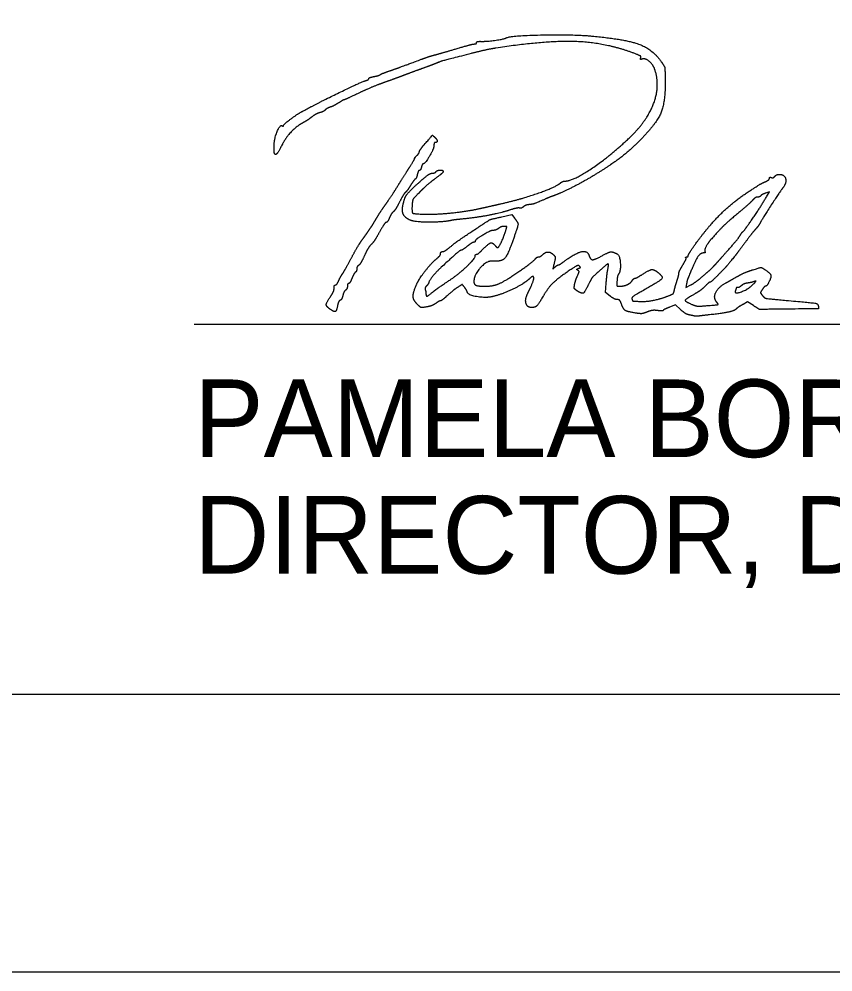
# Model space of a CAD drawing. Extents: x -21.1 to 50.3, y -4.9 to 22.1.
# Drawn here: x 24.436 to 25.904, y 0 to 1.718 of the extents above; entities that cross this region are included whole.
import ezdxf

# ---------------------------------------------------------------- set-up
doc = ezdxf.new("R2010")
doc.units = 0
for name, color, linetype in [('Default', 7, 'Continuous'), ('SH_Border', 7, 'Continuous'), ('SH_Cut_Line', 7, 'Continuous'), ('SH_Data', 7, 'Continuous'), ('SH_Text', 7, 'Continuous')]:
    doc.layers.add(name, color=color, linetype=linetype)

msp = doc.modelspace()

# ---------------------------------------------------------------- linework, layer by layer
at = {"layer": 'Default'}
for points in [[(25.7841, 1.3975), (25.7895, 1.4065), (25.7822, 1.4039)], [(25.3068, 1.3614), (25.3248, 1.3654), (25.3295, 1.3592)], [(25.5018, 1.2186), (25.4934, 1.2249), (25.4949, 1.242)], [(25.6398, 1.2406), (25.6387, 1.2341), (25.6474, 1.2385)], [(25.7606, 1.2012), (25.7499, 1.208), (25.7416, 1.2035)], [(25.6287, 1.1942), (25.6196, 1.2025), (25.609, 1.1984)]]:
    msp.add_lwpolyline(points, dxfattribs=at)
for points in [[(25.2702, 1.6777), (25.2798, 1.6775), (25.3108, 1.6818), (25.3142, 1.6839)], [(25.3142, 1.6839), (25.321, 1.6881), (25.438, 1.6904), (25.4724, 1.687)], [(25.4724, 1.687), (25.5317, 1.6812), (25.5792, 1.6629), (25.595, 1.6399)], [(25.2245, 1.6644), (25.2406, 1.6691), (25.2554, 1.673), (25.2575, 1.673)], [(25.2575, 1.673), (25.2595, 1.673), (25.2612, 1.6741), (25.2612, 1.6755)], [(25.2612, 1.6755), (25.2612, 1.6769), (25.2653, 1.6779), (25.2702, 1.6777)], [(25.5449, 1.6563), (25.4944, 1.6753), (25.3864, 1.6793), (25.296, 1.6655)], [(25.1616, 1.6454), (25.1696, 1.6483), (25.1804, 1.6519), (25.1856, 1.6532)], [(25.1856, 1.6532), (25.1909, 1.6546), (25.2084, 1.6596), (25.2245, 1.6644)], [(25.2516, 1.6558), (25.2006, 1.6426), (25.1963, 1.6414), (25.1856, 1.637)], [(25.296, 1.6655), (25.2868, 1.6641), (25.2668, 1.6597), (25.2516, 1.6558)], [(25.5572, 1.6477), (25.5582, 1.6502), (25.5548, 1.6526), (25.5449, 1.6563)], [(25.1052, 1.6248), (25.1199, 1.6299), (25.1264, 1.6322), (25.1616, 1.6454)], [(25.1856, 1.637), (25.183, 1.636), (25.1727, 1.6321), (25.1628, 1.6285)], [(25.5596, 1.6456), (25.557, 1.6446), (25.5563, 1.6452), (25.5572, 1.6477)], [(25.583, 1.6257), (25.5798, 1.6355), (25.5653, 1.6478), (25.5596, 1.6456)], [(25.595, 1.6399), (25.6, 1.6326), (25.6009, 1.6283), (25.6012, 1.6104)], [(25.0758, 1.6142), (25.0808, 1.6151), (25.0859, 1.6166), (25.0872, 1.6176)], [(25.0872, 1.6176), (25.0886, 1.6186), (25.0967, 1.6218), (25.1052, 1.6248)], [(25.1292, 1.6161), (25.1207, 1.6129), (25.1045, 1.607), (25.0932, 1.603)], [(25.1628, 1.6285), (25.1529, 1.625), (25.1378, 1.6194), (25.1292, 1.6161)], [(25.5375, 1.5045), (25.5685, 1.5339), (25.5923, 1.5974), (25.583, 1.6257)], [(24.9492, 1.5526), (24.9795, 1.5689), (25.0531, 1.6045), (25.0614, 1.607)], [(25.0932, 1.603), (25.082, 1.599), (25.0617, 1.5905), (25.048, 1.584)], [(25.0614, 1.607), (25.0644, 1.6078), (25.0668, 1.6094), (25.0668, 1.6105)], [(25.0668, 1.6105), (25.0668, 1.6116), (25.0709, 1.6132), (25.0758, 1.6142)], [(25.6012, 1.6104), (25.602, 1.5696), (25.5859, 1.5299), (25.5565, 1.5001)], [(25.048, 1.584), (25.0344, 1.5775), (25.0227, 1.5722), (25.0222, 1.5722)], [(25.0122, 1.5666), (25.0073, 1.5635), (25.0006, 1.5601), (24.9973, 1.5591)], [(25.0222, 1.5722), (25.0216, 1.5722), (25.0171, 1.5697), (25.0122, 1.5666)], [(24.9132, 1.526), (24.9132, 1.5281), (24.9386, 1.5469), (24.9492, 1.5526)], [(24.9785, 1.5491), (24.9749, 1.5482), (24.9683, 1.5446), (24.9636, 1.541)], [(24.9882, 1.5539), (24.9864, 1.5521), (24.982, 1.5499), (24.9785, 1.5491)], [(24.9973, 1.5591), (24.9941, 1.558), (24.99, 1.5557), (24.9882, 1.5539)], [(24.9477, 1.5306), (24.9373, 1.5253), (24.9174, 1.5045), (24.9112, 1.4923)], [(24.9636, 1.541), (24.959, 1.5374), (24.9519, 1.5328), (24.9477, 1.5306)], [(24.8961, 1.4881), (24.8962, 1.5013), (24.9068, 1.5279), (24.9109, 1.5254)], [(24.9109, 1.5254), (24.9122, 1.5246), (24.9132, 1.5249), (24.9132, 1.526)], [(25.1634, 1.4871), (25.182, 1.5092), (25.1813, 1.5086), (25.1854, 1.5052)], [(25.1868, 1.4954), (25.1855, 1.4954), (25.1844, 1.4931), (25.1844, 1.4903)], [(25.1854, 1.5052), (25.1896, 1.5017), (25.1906, 1.4954), (25.1868, 1.4954)], [(25.4208, 1.4258), (25.4349, 1.4258), (25.503, 1.4717), (25.5375, 1.5045)], [(25.5565, 1.5001), (25.5379, 1.4812), (25.5055, 1.4563), (25.475, 1.4374)], [(24.8974, 1.4744), (24.8966, 1.4752), (24.896, 1.4814), (24.8961, 1.4881)], [(24.9112, 1.4923), (24.9046, 1.4795), (24.8993, 1.4726), (24.8974, 1.4744)], [(25.1532, 1.4714), (25.1559, 1.4741), (25.158, 1.4772), (25.158, 1.4784)], [(25.158, 1.4784), (25.158, 1.4796), (25.1605, 1.4835), (25.1634, 1.4871)], [(25.1844, 1.4903), (25.1844, 1.4848), (25.1685, 1.457), (25.1653, 1.457)], [(25.1405, 1.451), (25.146, 1.4596), (25.1501, 1.4666), (25.1495, 1.4666)], [(25.1495, 1.4666), (25.1489, 1.4666), (25.1506, 1.4688), (25.1532, 1.4714)], [(25.1184, 1.4159), (25.125, 1.4266), (25.135, 1.4423), (25.1405, 1.451)], [(25.1582, 1.445), (25.157, 1.445), (25.1553, 1.4418), (25.1544, 1.4378)], [(25.1618, 1.451), (25.161, 1.4477), (25.1594, 1.445), (25.1582, 1.445)], [(25.1653, 1.457), (25.1642, 1.457), (25.1627, 1.4543), (25.1618, 1.451)], [(25.188, 1.4426), (25.1898, 1.4455), (25.2012, 1.4458), (25.2012, 1.443)], [(25.1505, 1.4292), (25.1493, 1.4285), (25.1455, 1.4233), (25.1421, 1.4178)], [(25.1496, 1.4161), (25.1653, 1.4307), (25.1781, 1.4402), (25.182, 1.4402)], [(25.1544, 1.4378), (25.1536, 1.4339), (25.1518, 1.43), (25.1505, 1.4292)], [(25.1862, 1.4299), (25.178, 1.4238), (25.1655, 1.4129), (25.1584, 1.4057)], [(25.182, 1.4402), (25.1845, 1.4402), (25.1872, 1.4413), (25.188, 1.4426)], [(25.2012, 1.443), (25.2012, 1.4419), (25.1945, 1.436), (25.1862, 1.4299)], [(25.475, 1.4374), (25.4558, 1.4256), (25.4145, 1.4046), (25.4004, 1.3995)], [(25.7814, 1.4245), (25.7857, 1.4264), (25.7892, 1.4292), (25.7892, 1.4308)], [(25.7892, 1.4308), (25.7892, 1.4323), (25.7908, 1.4329), (25.7927, 1.4322)], [(25.7927, 1.4322), (25.7945, 1.4315), (25.7974, 1.4325), (25.7989, 1.4344)], [(25.7989, 1.4344), (25.8005, 1.4363), (25.8042, 1.4378), (25.8071, 1.4378)], [(25.8071, 1.4378), (25.8166, 1.4378), (25.8203, 1.4218), (25.8129, 1.4128)], [(25.0967, 1.383), (25.102, 1.3905), (25.1118, 1.4053), (25.1184, 1.4159)], [(25.1283, 1.3814), (25.131, 1.3945), (25.1372, 1.4045), (25.1496, 1.4161)], [(25.1421, 1.4178), (25.1387, 1.4123), (25.1346, 1.4067), (25.1329, 1.4054)], [(25.3008, 1.3839), (25.3378, 1.3921), (25.404, 1.415), (25.4126, 1.4225)], [(25.4126, 1.4225), (25.4147, 1.4243), (25.4184, 1.4258), (25.4208, 1.4258)], [(25.7525, 1.4074), (25.7714, 1.4197), (25.7732, 1.4208), (25.7814, 1.4245)], [(25.8129, 1.4128), (25.8088, 1.4078), (25.7759, 1.3573), (25.7728, 1.3511)], [(25.1329, 1.4054), (25.1312, 1.4041), (25.1266, 1.3964), (25.1225, 1.3884)], [(25.1584, 1.4057), (25.1477, 1.3948), (25.1456, 1.3911), (25.145, 1.3829)], [(25.3848, 1.3933), (25.3677, 1.3858), (25.3628, 1.3841), (25.3562, 1.3834)], [(25.4004, 1.3995), (25.3958, 1.3978), (25.3888, 1.395), (25.3848, 1.3933)], [(25.6578, 1.3149), (25.6801, 1.3457), (25.7251, 1.3897), (25.7525, 1.4074)], [(25.7593, 1.3916), (25.7566, 1.3886), (25.7442, 1.3776), (25.7316, 1.367)], [(25.7413, 1.3346), (25.7442, 1.3366), (25.7724, 1.3781), (25.7841, 1.3975)], [(25.7682, 1.397), (25.766, 1.397), (25.762, 1.3946), (25.7593, 1.3916)], [(25.7735, 1.3992), (25.7727, 1.398), (25.7704, 1.397), (25.7682, 1.397)], [(25.7822, 1.4039), (25.7781, 1.4025), (25.7742, 1.4004), (25.7735, 1.3992)], [(25.08, 1.3574), (25.0838, 1.364), (25.0913, 1.3755), (25.0967, 1.383)], [(25.1225, 1.3884), (25.1185, 1.3805), (25.1135, 1.3725), (25.1113, 1.3707)], [(25.1436, 1.3546), (25.1332, 1.3585), (25.1261, 1.3709), (25.1283, 1.3814)], [(25.145, 1.3829), (25.1442, 1.3694), (25.1482, 1.3666), (25.1688, 1.366)], [(25.1688, 1.366), (25.1881, 1.3655), (25.2459, 1.3716), (25.2672, 1.3764)], [(25.2672, 1.3764), (25.2752, 1.3782), (25.2903, 1.3815), (25.3008, 1.3839)], [(25.3386, 1.3771), (25.337, 1.3777), (25.3289, 1.3761), (25.3206, 1.3734)], [(25.3454, 1.3793), (25.3433, 1.3775), (25.3403, 1.3765), (25.3386, 1.3771)], [(25.3562, 1.3834), (25.3524, 1.383), (25.3475, 1.3811), (25.3454, 1.3793)], [(25.0669, 1.3368), (25.0702, 1.3415), (25.0761, 1.3508), (25.08, 1.3574)], [(25.104, 1.3594), (25.1022, 1.355), (25.0996, 1.3514), (25.0983, 1.3514)], [(25.1113, 1.3707), (25.1091, 1.3689), (25.1059, 1.3638), (25.104, 1.3594)], [(25.2353, 1.3573), (25.2269, 1.3565), (25.2178, 1.3554), (25.2149, 1.3547)], [(25.3206, 1.3734), (25.3042, 1.3681), (25.2591, 1.3596), (25.2353, 1.3573)], [(25.2528, 1.335), (25.2845, 1.356), (25.2859, 1.3567), (25.3068, 1.3614)], [(25.3295, 1.3592), (25.3361, 1.3505), (25.336, 1.3456), (25.3282, 1.3231)], [(25.7316, 1.367), (25.712, 1.3505), (25.7003, 1.3391), (25.6836, 1.3202)], [(25.0983, 1.3514), (25.097, 1.3514), (25.0916, 1.3435), (25.0863, 1.3339)], [(25.2149, 1.3547), (25.2012, 1.3517), (25.1517, 1.3516), (25.1436, 1.3546)], [(25.301, 1.3405), (25.2984, 1.3386), (25.2945, 1.337), (25.2922, 1.337)], [(25.3109, 1.3441), (25.308, 1.3441), (25.3035, 1.3425), (25.301, 1.3405)], [(25.3142, 1.3376), (25.3159, 1.3434), (25.3154, 1.3442), (25.3109, 1.3441)], [(25.7728, 1.3511), (25.771, 1.3477), (25.7671, 1.3422), (25.7641, 1.339)], [(25.0534, 1.3176), (25.0575, 1.3234), (25.0636, 1.332), (25.0669, 1.3368)], [(25.0863, 1.3339), (25.0809, 1.3242), (25.0743, 1.3142), (25.0714, 1.3117)], [(25.2136, 1.307), (25.2273, 1.3181), (25.2254, 1.3167), (25.2528, 1.335)], [(25.2825, 1.3339), (25.2681, 1.3259), (25.2588, 1.3196), (25.2588, 1.3176)], [(25.2922, 1.337), (25.29, 1.337), (25.2856, 1.3356), (25.2825, 1.3339)], [(25.3282, 1.3231), (25.318, 1.2932), (25.306, 1.2801), (25.29, 1.2815)], [(25.2995, 1.3058), (25.3013, 1.3058), (25.311, 1.327), (25.3142, 1.3376)], [(25.7061, 1.2917), (25.7215, 1.3088), (25.735, 1.3251), (25.7374, 1.3295)], [(25.7374, 1.3295), (25.7386, 1.3316), (25.7404, 1.334), (25.7413, 1.3346)], [(25.7641, 1.339), (25.7612, 1.3358), (25.7522, 1.3244), (25.7444, 1.3138)], [(25.0345, 1.2854), (25.0408, 1.2973), (25.0493, 1.3118), (25.0534, 1.3176)], [(25.0714, 1.3117), (25.0686, 1.3091), (25.063, 1.3), (25.0591, 1.2914)], [(25.1998, 1.2986), (25.2017, 1.2986), (25.2079, 1.3024), (25.2136, 1.307)], [(25.2444, 1.3082), (25.2394, 1.3043), (25.2344, 1.301), (25.2333, 1.301)], [(25.2562, 1.3154), (25.2547, 1.3154), (25.2494, 1.3122), (25.2444, 1.3082)], [(25.2588, 1.3176), (25.2588, 1.3164), (25.2576, 1.3154), (25.2562, 1.3154)], [(25.2732, 1.3034), (25.2834, 1.3135), (25.2899, 1.3154), (25.2948, 1.3094)], [(25.2948, 1.3094), (25.2965, 1.3074), (25.2986, 1.3058), (25.2995, 1.3058)], [(25.6428, 1.2916), (25.6428, 1.293), (25.6496, 1.3035), (25.6578, 1.3149)], [(25.6836, 1.3202), (25.6778, 1.3136), (25.6715, 1.3008), (25.673, 1.2984)], [(25.7444, 1.3138), (25.7365, 1.3031), (25.7288, 1.2929), (25.7273, 1.2911)], [(25.0591, 1.2914), (25.0552, 1.2828), (25.0505, 1.275), (25.0486, 1.2739)], [(25.191, 1.2874), (25.194, 1.2898), (25.1964, 1.2933), (25.1964, 1.2952)], [(25.1964, 1.2952), (25.1964, 1.2971), (25.1979, 1.2986), (25.1998, 1.2986)], [(25.2333, 1.301), (25.2314, 1.301), (25.2229, 1.2937), (25.1976, 1.2705)], [(25.2128, 1.2472), (25.2283, 1.2576), (25.2588, 1.2864), (25.2588, 1.2907)], [(25.2588, 1.2907), (25.2588, 1.2924), (25.2599, 1.2938), (25.2612, 1.2938)], [(25.2612, 1.2938), (25.2626, 1.2938), (25.268, 1.2981), (25.2732, 1.3034)], [(25.3676, 1.286), (25.3686, 1.2876), (25.371, 1.289), (25.3728, 1.289)], [(25.3728, 1.289), (25.3746, 1.289), (25.3778, 1.2908), (25.38, 1.2929)], [(25.38, 1.2929), (25.385, 1.2979), (25.3949, 1.2979), (25.3999, 1.293)], [(25.3999, 1.293), (25.403, 1.2898), (25.4033, 1.2874), (25.4012, 1.2782)], [(25.418, 1.2803), (25.4382, 1.2955), (25.461, 1.3011), (25.4639, 1.2917)], [(25.4639, 1.2917), (25.4664, 1.2841), (25.4744, 1.284), (25.4877, 1.2913)], [(25.4877, 1.2913), (25.4997, 1.2979), (25.5069, 1.2986), (25.5151, 1.294)], [(25.5151, 1.294), (25.5195, 1.2916), (25.5212, 1.2636), (25.5173, 1.2584)], [(25.6387, 1.2876), (25.6379, 1.2884), (25.6385, 1.289), (25.64, 1.289)], [(25.64, 1.289), (25.6416, 1.289), (25.6428, 1.2902), (25.6428, 1.2916)], [(25.6707, 1.2962), (25.6644, 1.2962), (25.6548, 1.281), (25.6428, 1.2518)], [(25.673, 1.2984), (25.6737, 1.2972), (25.6727, 1.2962), (25.6707, 1.2962)], [(25.6905, 1.2742), (25.6937, 1.2777), (25.7007, 1.2856), (25.7061, 1.2917)], [(25.7273, 1.2911), (25.714, 1.2747), (25.7095, 1.2695), (25.6976, 1.2574)], [(25.019, 1.2578), (25.0212, 1.2611), (25.0282, 1.2735), (25.0345, 1.2854)], [(25.0486, 1.2739), (25.0467, 1.2728), (25.0452, 1.2699), (25.0452, 1.2674)], [(25.1529, 1.2391), (25.1574, 1.2496), (25.1807, 1.2791), (25.191, 1.2874)], [(25.29, 1.2815), (25.2796, 1.2823), (25.2564, 1.257), (25.2564, 1.2447)], [(25.3248, 1.2541), (25.3434, 1.2665), (25.3658, 1.2832), (25.3676, 1.286)], [(25.4012, 1.2782), (25.3988, 1.268), (25.3989, 1.2675), (25.4027, 1.2709)], [(25.4027, 1.2709), (25.405, 1.273), (25.4076, 1.2746), (25.4086, 1.2746)], [(25.4086, 1.2746), (25.4096, 1.2746), (25.4138, 1.2772), (25.418, 1.2803)], [(25.4467, 1.2725), (25.4449, 1.2743), (25.439, 1.2716), (25.4265, 1.2631)], [(25.445, 1.2684), (25.448, 1.2695), (25.4485, 1.2707), (25.4467, 1.2725)], [(25.4979, 1.2668), (25.4997, 1.2763), (25.4971, 1.2767), (25.4878, 1.2685)], [(25.626, 1.26), (25.626, 1.2618), (25.6292, 1.2684), (25.6331, 1.2747)], [(25.6331, 1.2747), (25.6369, 1.281), (25.6395, 1.2868), (25.6387, 1.2876)], [(25.6704, 1.2554), (25.6784, 1.2622), (25.6874, 1.2706), (25.6905, 1.2742)], [(25.0122, 1.2452), (25.0137, 1.2488), (25.0168, 1.2545), (25.019, 1.2578)], [(25.0427, 1.2614), (25.0414, 1.2605), (25.0385, 1.2556), (25.0365, 1.2504)], [(25.0452, 1.2674), (25.0452, 1.2649), (25.0441, 1.2622), (25.0427, 1.2614)], [(25.1976, 1.2705), (25.1885, 1.2621), (25.1748, 1.2451), (25.1748, 1.2421)], [(25.2764, 1.2362), (25.2894, 1.2362), (25.3085, 1.2433), (25.3248, 1.2541)], [(25.4265, 1.2631), (25.4067, 1.2496), (25.3895, 1.2326), (25.3812, 1.2182)], [(25.438, 1.2394), (25.4388, 1.2436), (25.4411, 1.2506), (25.4431, 1.255)], [(25.4438, 1.2649), (25.4416, 1.2663), (25.4419, 1.2672), (25.445, 1.2684)], [(25.4431, 1.255), (25.446, 1.2613), (25.4461, 1.2635), (25.4438, 1.2649)], [(25.4878, 1.2685), (25.4719, 1.2544), (25.4681, 1.25), (25.4626, 1.2387)], [(25.4949, 1.242), (25.4957, 1.2513), (25.497, 1.2625), (25.4979, 1.2668)], [(25.5173, 1.2584), (25.5161, 1.2568), (25.5147, 1.2511), (25.5144, 1.2458)], [(25.5469, 1.2506), (25.5481, 1.2506), (25.5542, 1.2539), (25.5604, 1.2578)], [(25.5886, 1.2608), (25.5983, 1.2532), (25.5915, 1.2453), (25.5599, 1.2275)], [(25.5604, 1.2578), (25.5734, 1.266), (25.581, 1.2668), (25.5886, 1.2608)], [(25.6225, 1.2458), (25.6245, 1.2518), (25.626, 1.2581), (25.626, 1.26)], [(25.6474, 1.2385), (25.6521, 1.241), (25.6625, 1.2485), (25.6704, 1.2554)], [(25.6976, 1.2574), (25.6901, 1.2497), (25.6831, 1.2434), (25.682, 1.2434)], [(25.7304, 1.2534), (25.7384, 1.2579), (25.7515, 1.2636), (25.7597, 1.266)], [(25.7597, 1.266), (25.7738, 1.2703), (25.775, 1.2703), (25.7808, 1.2664)], [(25.7808, 1.2664), (25.7904, 1.2601), (25.7929, 1.2527), (25.7882, 1.2438)], [(25.0044, 1.233), (25.0044, 1.2361), (25.0055, 1.2386), (25.0069, 1.2386)], [(25.0069, 1.2386), (25.0082, 1.2386), (25.0106, 1.2416), (25.0122, 1.2452)], [(25.0306, 1.241), (25.0294, 1.241), (25.0284, 1.239), (25.0284, 1.2365)], [(25.0365, 1.2504), (25.0344, 1.2452), (25.0317, 1.241), (25.0306, 1.241)], [(25.1546, 1.2034), (25.147, 1.211), (25.1464, 1.2239), (25.1529, 1.2391)], [(25.1711, 1.2369), (25.169, 1.2349), (25.168, 1.2316), (25.1687, 1.2297)], [(25.1748, 1.2421), (25.1748, 1.2413), (25.1731, 1.239), (25.1711, 1.2369)], [(25.1812, 1.2249), (25.1888, 1.231), (25.194, 1.2347), (25.2128, 1.2472)], [(25.2398, 1.2337), (25.2354, 1.2395), (25.2353, 1.2395), (25.2285, 1.2351)], [(25.2564, 1.2447), (25.2564, 1.2395), (25.2642, 1.2362), (25.2764, 1.2362)], [(25.3568, 1.25), (25.3472, 1.2408), (25.3085, 1.222), (25.29, 1.2176)], [(25.3539, 1.2242), (25.358, 1.2319), (25.3644, 1.2482), (25.3644, 1.2509)], [(25.3644, 1.2509), (25.3644, 1.254), (25.3605, 1.2535), (25.3568, 1.25)], [(25.4426, 1.2279), (25.4377, 1.2312), (25.4369, 1.2331), (25.438, 1.2394)], [(25.4626, 1.2387), (25.456, 1.225), (25.4511, 1.2224), (25.4426, 1.2279)], [(25.5144, 1.2458), (25.5139, 1.2382), (25.5146, 1.2362), (25.5177, 1.2362)], [(25.5177, 1.2362), (25.526, 1.2362), (25.538, 1.2411), (25.5413, 1.2457)], [(25.5413, 1.2457), (25.5432, 1.2484), (25.5457, 1.2506), (25.5469, 1.2506)], [(25.6178, 1.2288), (25.6184, 1.2322), (25.6206, 1.2399), (25.6225, 1.2458)], [(25.6428, 1.2518), (25.6417, 1.2492), (25.6403, 1.2441), (25.6398, 1.2406)], [(25.682, 1.2434), (25.6809, 1.2434), (25.6771, 1.2403), (25.6734, 1.2365)], [(25.6938, 1.208), (25.6877, 1.2154), (25.6975, 1.2351), (25.7109, 1.2424)], [(25.7109, 1.2424), (25.7137, 1.2439), (25.7225, 1.2488), (25.7304, 1.2534)], [(25.7278, 1.2281), (25.7253, 1.2215), (25.7508, 1.2305), (25.7592, 1.2391)], [(25.7388, 1.2374), (25.7366, 1.2354), (25.7336, 1.2338), (25.732, 1.2338)], [(25.7498, 1.2419), (25.746, 1.2414), (25.741, 1.2394), (25.7388, 1.2374)], [(25.7616, 1.2447), (25.759, 1.2437), (25.7537, 1.2424), (25.7498, 1.2419)], [(25.7592, 1.2391), (25.7647, 1.2447), (25.7653, 1.246), (25.7616, 1.2447)], [(25.7882, 1.2438), (25.7861, 1.2396), (25.7834, 1.2362), (25.7822, 1.2362)], [(24.9986, 1.2187), (25.0018, 1.2234), (25.0044, 1.2298), (25.0044, 1.233)], [(25.025, 1.2291), (25.0231, 1.2276), (25.0208, 1.223), (25.02, 1.2191)], [(25.0284, 1.2365), (25.0284, 1.234), (25.0269, 1.2307), (25.025, 1.2291)], [(25.1687, 1.2297), (25.1694, 1.2278), (25.17, 1.2247), (25.17, 1.2228)], [(25.17, 1.2228), (25.17, 1.218), (25.1735, 1.2186), (25.1812, 1.2249)], [(25.2285, 1.2351), (25.2203, 1.2297), (25.2178, 1.2276), (25.2066, 1.2176)], [(25.2444, 1.2263), (25.2443, 1.2271), (25.2423, 1.2304), (25.2398, 1.2337)], [(25.29, 1.2176), (25.2772, 1.2145), (25.2446, 1.2207), (25.2444, 1.2263)], [(25.3606, 1.1978), (25.3522, 1.1978), (25.3482, 1.2136), (25.3539, 1.2242)], [(25.5599, 1.2275), (25.5467, 1.2201), (25.5404, 1.2153), (25.5413, 1.2131)], [(25.6051, 1.2181), (25.6139, 1.2215), (25.6168, 1.2239), (25.6178, 1.2288)], [(25.6555, 1.2229), (25.6375, 1.2125), (25.6365, 1.2092), (25.6494, 1.2036)], [(25.6734, 1.2365), (25.6698, 1.2326), (25.6617, 1.2265), (25.6555, 1.2229)], [(25.7292, 1.2328), (25.7292, 1.2323), (25.7286, 1.2301), (25.7278, 1.2281)], [(25.732, 1.2338), (25.7305, 1.2338), (25.7292, 1.2334), (25.7292, 1.2328)], [(25.7764, 1.2304), (25.7729, 1.2251), (25.7729, 1.2242), (25.7767, 1.2195)], [(25.7822, 1.2362), (25.7811, 1.2362), (25.7785, 1.2336), (25.7764, 1.2304)], [(24.9969, 1.195), (24.9899, 1.1999), (24.9904, 1.2066), (24.9986, 1.2187)], [(25.0152, 1.2107), (25.0135, 1.21), (25.0114, 1.2059), (25.0106, 1.2015)], [(25.02, 1.2191), (25.0191, 1.2151), (25.017, 1.2114), (25.0152, 1.2107)], [(25.1708, 1.1988), (25.1621, 1.1975), (25.16, 1.1981), (25.1546, 1.2034)], [(25.1873, 1.2051), (25.1838, 1.2025), (25.1763, 1.1997), (25.1708, 1.1988)], [(25.1958, 1.2098), (25.1947, 1.2098), (25.1909, 1.2077), (25.1873, 1.2051)], [(25.2066, 1.2176), (25.2018, 1.2133), (25.1969, 1.2098), (25.1958, 1.2098)], [(25.3812, 1.2182), (25.373, 1.2041), (25.3667, 1.1978), (25.3606, 1.1978)], [(25.5148, 1.2122), (25.5122, 1.2122), (25.5063, 1.2151), (25.5018, 1.2186)], [(25.5223, 1.2044), (25.5204, 1.2096), (25.5179, 1.2122), (25.5148, 1.2122)], [(25.5477, 1.1879), (25.5326, 1.1903), (25.5258, 1.1948), (25.5223, 1.2044)], [(25.5413, 1.2131), (25.5426, 1.2097), (25.5433, 1.2095), (25.5552, 1.2088)], [(25.5552, 1.2088), (25.5658, 1.2082), (25.5919, 1.2131), (25.6051, 1.2181)], [(25.6494, 1.2036), (25.6563, 1.2007), (25.6627, 1.2001), (25.6762, 1.2012)], [(25.6762, 1.2012), (25.6958, 1.2028), (25.6975, 1.2034), (25.6938, 1.208)], [(25.7416, 1.2035), (25.737, 1.201), (25.7317, 1.1975), (25.7299, 1.1957)], [(25.7767, 1.2195), (25.7804, 1.2149), (25.7853, 1.2139), (25.8192, 1.2108)], [(25.8192, 1.2108), (25.8683, 1.2063), (25.8766, 1.2047), (25.8775, 1.1999)], [(25.0106, 1.2015), (25.0088, 1.1917), (25.0046, 1.1897), (24.9969, 1.195)], [(25.5688, 1.1898), (25.5618, 1.187), (25.5562, 1.1865), (25.5477, 1.1879)], [(25.5876, 1.1924), (25.5819, 1.1931), (25.5746, 1.1922), (25.5688, 1.1898)], [(25.5977, 1.1927), (25.5973, 1.1918), (25.5928, 1.1917), (25.5876, 1.1924)], [(25.609, 1.1984), (25.6032, 1.1962), (25.5981, 1.1936), (25.5977, 1.1927)], [(25.6434, 1.1848), (25.6404, 1.1854), (25.6338, 1.1897), (25.6287, 1.1942)], [(25.7299, 1.1957), (25.7261, 1.192), (25.7046, 1.1871), (25.6812, 1.1847)], [(25.8072, 1.1948), (25.7715, 1.1944), (25.7711, 1.1945), (25.7606, 1.2012)], [(25.8775, 1.1999), (25.8783, 1.1957), (25.8764, 1.1956), (25.8072, 1.1948)], [(25.6536, 1.1826), (25.651, 1.1832), (25.6464, 1.1841), (25.6434, 1.1848)], [(25.662, 1.1824), (25.6601, 1.182), (25.6563, 1.1821), (25.6536, 1.1826)], [(25.6812, 1.1847), (25.6727, 1.1838), (25.664, 1.1827), (25.662, 1.1824)]]:
    msp.add_open_spline(points, degree=2, dxfattribs=at)
at = {"layer": 'SH_Border'}
msp.add_lwpolyline([(1.5, 21.5), (33.5, 21.5), (33.5, 0.5), (1.5, 0.5)], close=True, dxfattribs=at)
at = {"layer": 'SH_Cut_Line'}
msp.add_lwpolyline([(0, 0), (34, 0), (34, 22), (0, 22)], close=True, dxfattribs=at)
at = {"layer": 'SH_Data'}
msp.add_line((24.7523, 1.1681), (28.2523, 1.1681), dxfattribs=at)
at = {"layer": 'SH_Text'}
for p, q in [((25.2146, 1.3731), (25.2146, 1.3731)), ((25.58, 1.2833), (25.58, 1.2833)), ((25.5352, 1.2416), (25.5352, 1.2416))]:
    msp.add_line(p, q, dxfattribs=at)

# ---------------------------------------------------------------- texts
for s, p in [('PAMELA BORATYN', (24.7523, 0.9281)), ('DIRECTOR, DEPARTMENT OF TRANSPORTATION', (24.7523, 0.7181))]:
    msp.add_text(s, height=0.14, dxfattribs=at).set_placement(p)

doc.saveas('drawing.dxf')
